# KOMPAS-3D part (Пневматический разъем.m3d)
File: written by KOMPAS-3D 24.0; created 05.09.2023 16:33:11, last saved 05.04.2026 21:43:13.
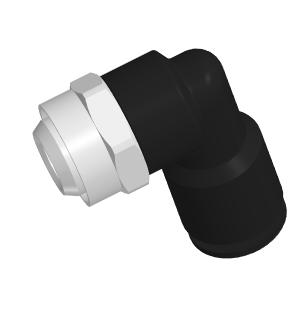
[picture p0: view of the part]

Document properties: Полное имя файла: E:\Работа\Зайцев\Аксессуары для пневмоприводов\Электропневматические позиционеры DN.ru\ЭИП Электропневматический позиционер DN.ru\ЭИП-1500 Электропневматический позиционер DN.ru\5-25\Пневматический разъем.m3d

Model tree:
1. Операция без истории:12
2. Элемент выдавливания:1  (with: Грань.Операция без истории:12)
     Расстояние 1 = 3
